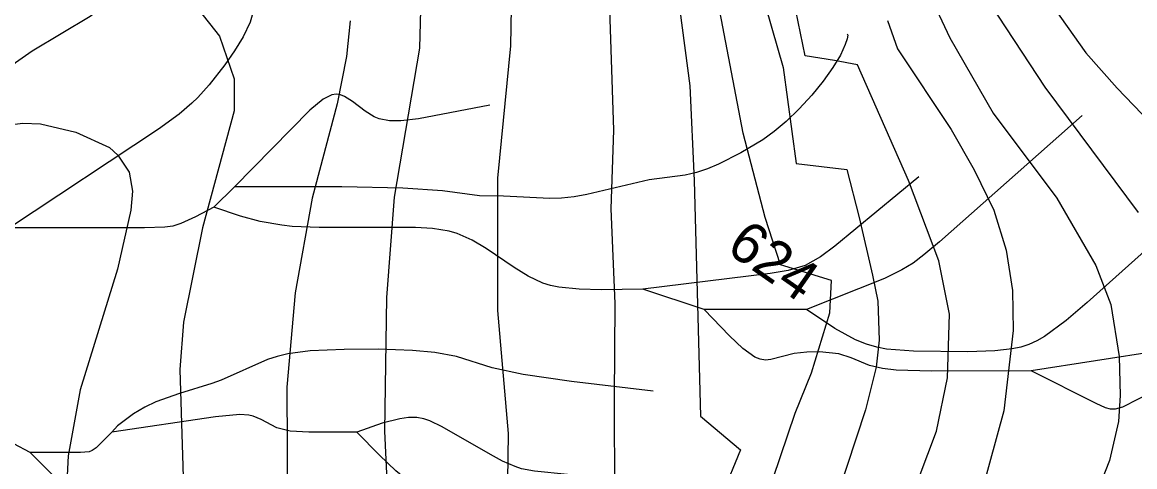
# Model space of a CAD drawing. Extents: x -709584 to -702006, y -1161789 to -1157496.
# Drawn here: x -707673.9 to -707401.6, y -1161265.5 to -1161156.7 of the extents above; entities that cross this region are included whole.
import ezdxf

# ---------------------------------------------------------------- set-up
doc = ezdxf.new("R2010")
doc.units = 0
for name, color, linetype in [('120_vrstevnice hlavní', 7, 'Continuous'), ('121_vrstevnice hlavní_popis', 7, 'Continuous'), ('122_vrstevnice základní', 7, 'Continuous'), ('411_akumulovaný odtok', 7, 'Continuous')]:
    doc.layers.add(name, color=color, linetype=linetype)

msp = doc.modelspace()

# ---------------------------------------------------------------- linework, layer by layer
at = {"layer": '120_vrstevnice hlavní'}
for points in [[(-707595.55, -1161031.98), (-707575.3, -1161055.13), (-707565.31, -1161068), (-707561.41, -1161075.96), (-707557.07, -1161087.24), (-707540.15, -1161115.88), (-707538.41, -1161119.64), (-707533.49, -1161134.68), (-707530.17, -1161153.48), (-707529.2, -1161183.13), (-707529.88, -1161202.37), (-707528.86, -1161225.52), (-707529.01, -1161248.66), (-707528.99, -1161272.92), (-707530.12, -1161282.34), (-707527.85, -1161284.68), (-707520.7, -1161289.88), (-707524.46, -1161298.17), (-707529.63, -1161309.29), (-707534.15, -1161320.98), (-707537.75, -1161331.12), (-707545.29, -1161343.18), (-707552.99, -1161352.64), (-707566.55, -1161362.44)], [(-707462.13, -1161156.29), (-707459.66, -1161163.19), (-707446.56, -1161182.99), (-707440.92, -1161192.83), (-707436.15, -1161202.66), (-707433.11, -1161212.5), (-707431.52, -1161222.33), (-707431.37, -1161232.17), (-707433.69, -1161251.84), (-707439.04, -1161271.51)], [(-707691.16, -1161183.57), (-707673.8, -1161181.4), (-707669.46, -1161181.54), (-707660.78, -1161183.57), (-707652.54, -1161187.33), (-707650.51, -1161189.21), (-707647.76, -1161193.41), (-707646.89, -1161198.03), (-707647.33, -1161202.66), (-707650.59, -1161217.15), (-707659.77, -1161246.64), (-707662.66, -1161262.84), (-707663.09, -1161270.94), (-707661.5, -1161292.34), (-707662.08, -1161305.36), (-707664.25, -1161318.38), (-707666.57, -1161327.06), (-707672.64, -1161340.08), (-707681.46, -1161353.24)]]:
    msp.add_lwpolyline(points, dxfattribs=at)
at = {"layer": '122_vrstevnice základní'}
for points in [[(-707482.27, -1161164.89), (-707493.14, -1161112.12)], [(-707497.72, -1161132.85), (-707487.65, -1161167.77)], [(-707454.77, -1161143.59), (-707446.85, -1161160.55), (-707436.29, -1161178.94), (-707420.67, -1161199.77), (-707411.12, -1161216.26), (-707407.51, -1161225.81), (-707405.48, -1161238.53), (-707405.19, -1161248.08), (-707405.63, -1161254.45), (-707407.8, -1161263.99), (-707411.56, -1161273.54), (-707424.43, -1161301.6), (-707430.51, -1161321.85), (-707438.75, -1161359.46), (-707443.09, -1161376.81), (-707446.27, -1161385.49), (-707449.89, -1161391.28), (-707459.72, -1161400.83), (-707475.35, -1161410.08), (-707494.15, -1161418.47), (-707528.87, -1161431.2), (-707554.9, -1161444.65), (-707571.1, -1161457.09), (-707587.4, -1161472.28)], [(-707488.36, -1161216.11), (-707492.07, -1161204.47), (-707497.48, -1161183.86), (-707505.29, -1161142.78)], [(-707660.66, -1161419.36), (-707668.58, -1161408.8), (-707654.42, -1161394.03), (-707622.59, -1161363.22), (-707612.32, -1161351.36), (-707601.48, -1161336.03), (-707594.39, -1161321.85), (-707591.5, -1161313.61), (-707585.13, -1161286.56), (-707584.41, -1161272.38), (-707585.13, -1161256.76), (-707584.7, -1161224.07), (-707582.82, -1161199.48), (-707576.6, -1161163.03), (-707576.16, -1161147.41)], [(-707400.71, -1161203.24), (-707423.56, -1161172.58), (-707438.75, -1161149.43)], [(-707630.84, -1161153.48), (-707625.63, -1161160.14), (-707622.02, -1161170.55), (-707622.02, -1161178.36), (-707629.83, -1161207), (-707634.46, -1161230.15), (-707635.32, -1161241.72), (-707634.31, -1161275.85), (-707634.6, -1161283.95), (-707636.33, -1161295.53), (-707639.08, -1161307.1), (-707643.42, -1161320.11), (-707646.75, -1161327.93), (-707653.55, -1161340.94), (-707664.97, -1161359.17), (-707678.28, -1161375.66), (-707706.34, -1161405.17), (-707719.94, -1161421.08), (-707728.1, -1161434.06), (-707740.16, -1161454.79), (-707746.94, -1161467.23), (-707740.16, -1161476.28)], [(-707596.69, -1161372.62), (-707603.85, -1161362.44), (-707594.81, -1161350.38), (-707589.91, -1161343.6), (-707579.74, -1161330.78), (-707568.64, -1161316.06), (-707564.3, -1161307.1), (-707558.32, -1161292.38), (-707556.78, -1161285.11), (-707555.05, -1161268.91), (-707554.9, -1161257.34), (-707557.5, -1161227.25), (-707557.5, -1161194.85), (-707554.32, -1161162.45), (-707554.18, -1161153.2)], [(-707422.7, -1161151.17), (-707413.58, -1161164.19), (-707405.92, -1161172.87), (-707365.27, -1161215.1)], [(-707512.95, -1161153.77), (-707510.49, -1161172.29), (-707509.48, -1161195.43), (-707507.89, -1161253.09), (-707498.09, -1161261.38), (-707502.61, -1161272.31), (-707512.41, -1161296.44), (-707517.87, -1161313.75), (-707523.66, -1161329.37), (-707528.14, -1161337.18), (-707534.9, -1161348.12), (-707543.57, -1161357.92), (-707550.73, -1161363.95), (-707560.15, -1161370.36), (-707573.71, -1161378.27)], [(-707593.67, -1161156.38), (-707594.53, -1161165.06), (-707596.85, -1161176.63), (-707602.92, -1161199.77), (-707607.12, -1161222.91), (-707609.14, -1161246.06), (-707609, -1161275.56), (-707610.16, -1161286.27), (-707612.04, -1161294.08), (-707616.52, -1161307.1), (-707621.44, -1161317.51), (-707631.42, -1161335.74), (-707637.93, -1161346.15)], [(-707456.98, -1161195.43), (-707469.46, -1161167.15), (-707475.11, -1161166.02), (-707482.27, -1161164.89)], [(-707487.65, -1161167.77), (-707484.53, -1161191.28), (-707472.1, -1161192.78), (-707469.08, -1161204.47), (-707465.8, -1161218.57), (-707464.5, -1161224.94), (-707464.21, -1161234.49), (-707464.93, -1161241.14), (-707467.54, -1161251.55), (-707478.96, -1161286.27)], [(-707622.16, -1161470.26), (-707615.07, -1161460.85), (-707605.09, -1161450.58), (-707591.35, -1161438.29), (-707579.49, -1161428.89), (-707566.47, -1161419.78), (-707545.79, -1161409.79), (-707530.6, -1161404.01), (-707503.12, -1161391.42), (-707497.62, -1161387.95), (-707489.52, -1161381.44), (-707481.85, -1161372.48), (-707478.67, -1161366.69), (-707476.5, -1161360.9), (-707474.62, -1161352.66), (-707473.32, -1161345.28), (-707473.18, -1161340.08), (-707470.14, -1161316.64), (-707462.91, -1161290.61), (-707450.18, -1161256.76), (-707447.43, -1161243.74), (-707447, -1161228.12), (-707449.6, -1161215.1), (-707456.98, -1161195.43)], [(-707674.23, -1161496.63), (-707670.46, -1161486.83), (-707661.42, -1161468.36), (-707653.65, -1161456.95), (-707635.86, -1161435.98), (-707626.76, -1161428.41), (-707610.93, -1161415.59), (-707591.72, -1161403.15), (-707559.24, -1161384.48), (-707548.25, -1161377.83), (-707535.08, -1161368.57), (-707527.42, -1161362.35), (-707515.99, -1161350.63), (-707511.51, -1161343.84), (-707506.16, -1161332.27), (-707502.39, -1161320.69), (-707501.09, -1161314.91), (-707498.06, -1161293.21), (-707490.12, -1161268.28), (-707484.77, -1161252.37), (-707480.76, -1161242.54), (-707476.24, -1161227.84), (-707475.86, -1161219.92), (-707488.36, -1161216.11)]]:
    msp.add_lwpolyline(points, dxfattribs=at)
at = {"layer": '411_akumulovaný odtok'}
for p, q in [((-707621.99, -1161197), (-707626.99, -1161202)), ((-707506.99, -1161227), (-707521.99, -1161222)), ((-707481.99, -1161227), (-707506.99, -1161227)), ((-707394.49, -1161237), (-707426.99, -1161242))]:
    msp.add_line(p, q, dxfattribs=at)
for points in [[(-707661.99, -1161137), (-707663.17, -1161138.18), (-707664.12, -1161139.85), (-707664.33, -1161140.81), (-707664.21, -1161141.89), (-707663.75, -1161142.94), (-707663.02, -1161143.93), (-707662.11, -1161144.82), (-707657.05, -1161148.45), (-707655.34, -1161149.87), (-707654.26, -1161151.27), (-707654.12, -1161151.96), (-707654.33, -1161152.63), (-707655.49, -1161153.95), (-707657.25, -1161155.26), (-707671.46, -1161163.74), (-707675.57, -1161166.65), (-707676.56, -1161167.67), (-707678.42, -1161170.19), (-707680.01, -1161172.94), (-707681.99, -1161177)], [(-707606.99, -1161137), (-707608.16, -1161137.48), (-707610.58, -1161139.1), (-707611.94, -1161140.32), (-707613.24, -1161141.81), (-707614.35, -1161143.56), (-707615.26, -1161145.5), (-707615.97, -1161147.53), (-707617.62, -1161154.95), (-707618.14, -1161156.65), (-707619.82, -1161160.27), (-707621.96, -1161163.73), (-707624.33, -1161167.1), (-707628.16, -1161172), (-707630.9, -1161175.09), (-707632.36, -1161176.54), (-707635.51, -1161179.2), (-707640.54, -1161182.85), (-707676.99, -1161207)], [(-707471.99, -1161159.5), (-707471.87, -1161159.87), (-707472.02, -1161160.79), (-707472.46, -1161162.18), (-707473.67, -1161164.72), (-707475.5, -1161167.75), (-707477.88, -1161171.08), (-707480.66, -1161174.51), (-707483.72, -1161177.87), (-707486.93, -1161180.96), (-707489.87, -1161183.43), (-707492.66, -1161185.44), (-707498.03, -1161188.68), (-707503.47, -1161191.45), (-707506.2, -1161192.59), (-707508.92, -1161193.51), (-707511.63, -1161194.14), (-707520.48, -1161195.27), (-707535.72, -1161198.89), (-707538.82, -1161199.45), (-707541.91, -1161199.79), (-707544.82, -1161199.85), (-707556.1, -1161199.24), (-707562.02, -1161199.17), (-707571.05, -1161197.96), (-707580.78, -1161197.3), (-707595.72, -1161197.01), (-707621.99, -1161197)], [(-707559.49, -1161177), (-707576.96, -1161180.33), (-707581.24, -1161180.83), (-707583.99, -1161180.85), (-707586.59, -1161180.35), (-707587.75, -1161179.85), (-707589.94, -1161178.48), (-707593.04, -1161176.13), (-707595.05, -1161174.85), (-707596.05, -1161174.44), (-707597.05, -1161174.28), (-707598.13, -1161174.43), (-707600.29, -1161175.52), (-707603.54, -1161178.21), (-707621.99, -1161197)], [(-707414.49, -1161179.5), (-707449.45, -1161210.45), (-707453.26, -1161213.65), (-707455.89, -1161215.64), (-707458.61, -1161217.34), (-707462.84, -1161219.41), (-707481.99, -1161227)], [(-707454.49, -1161194.5), (-707475.05, -1161211.52), (-707478.57, -1161214.14), (-707482.3, -1161216.27), (-707486.45, -1161217.5), (-707490.82, -1161218.24), (-707521.99, -1161222)], [(-707384.49, -1161199.5), (-707413.28, -1161225.3), (-707418.41, -1161229.72), (-707423.74, -1161233.64), (-707425.6, -1161234.72), (-707427.54, -1161235.59), (-707429.53, -1161236.21), (-707431.59, -1161236.65), (-707435.86, -1161237.13), (-707442.46, -1161237.36), (-707455.81, -1161237.21), (-707462.38, -1161236.73), (-707464.75, -1161236.27), (-707467.3, -1161235.5), (-707469.95, -1161234.41), (-707475.03, -1161231.68), (-707481.99, -1161227)], [(-707626.99, -1161202), (-707631.53, -1161204.36), (-707635.09, -1161205.97), (-707637.09, -1161206.58), (-707639.02, -1161206.87), (-707643.98, -1161207.05), (-707676.99, -1161207)], [(-707521.99, -1161222), (-707532.17, -1161222.18), (-707537.64, -1161222.05), (-707542.6, -1161221.57), (-707544.62, -1161221.15), (-707546.51, -1161220.57), (-707550.1, -1161218.85), (-707553.55, -1161216.7), (-707560.34, -1161212.08), (-707563.82, -1161210), (-707567.44, -1161208.38), (-707569.41, -1161207.84), (-707573.48, -1161207.2), (-707577.67, -1161206.93), (-707601.24, -1161206.91), (-707607.81, -1161206.68), (-707610.39, -1161206.4), (-707615.66, -1161205.43), (-707620.48, -1161204.15), (-707626.99, -1161202)], [(-707426.99, -1161242), (-707451.39, -1161242.1), (-707460, -1161241.84), (-707463.33, -1161241.46), (-707466.51, -1161240.72), (-707471.05, -1161238.85), (-707474.08, -1161237.9), (-707478.76, -1161237.37), (-707481.92, -1161237.42), (-707484.99, -1161237.77), (-707490.7, -1161239.29), (-707492.02, -1161239.4), (-707493.31, -1161239.18), (-707494.59, -1161238.65), (-707497.56, -1161236.52), (-707500.84, -1161233.48), (-707506.99, -1161227)], [(-707519.49, -1161247), (-707539.48, -1161244.66), (-707551.27, -1161242.95), (-707558.88, -1161241.31), (-707567.65, -1161238.52), (-707572.91, -1161237.52), (-707578.36, -1161237.03), (-707586.71, -1161236.76), (-707595.11, -1161236.77), (-707603.45, -1161237.16), (-707608.87, -1161237.87), (-707611.51, -1161238.48), (-707613.86, -1161239.25), (-707625.22, -1161244.28), (-707627.53, -1161245.16), (-707635.43, -1161247.55), (-707641.24, -1161249.64), (-707643.94, -1161250.92), (-707646.64, -1161252.52), (-707650.58, -1161255.52), (-707651.99, -1161257)], [(-707396.99, -1161247), (-707404.63, -1161250.9), (-707406.4, -1161251.41), (-707407.57, -1161251.39), (-707408.75, -1161251.07), (-707411.1, -1161250.03), (-707426.99, -1161242)], [(-707591.99, -1161257), (-707603.75, -1161257.07), (-707608.37, -1161256.76), (-707611.58, -1161255.99), (-707615.41, -1161253.95), (-707617.36, -1161253.11), (-707618.43, -1161252.87), (-707620.69, -1161252.73), (-707626.61, -1161253.27), (-707651.99, -1161257)], [(-707511.99, -1161272), (-707512.87, -1161272.93), (-707513.93, -1161273.56), (-707515.32, -1161274.07), (-707516.94, -1161274.32), (-707518.75, -1161274.29), (-707520.67, -1161274.02), (-707524.47, -1161272.95), (-707532.4, -1161269.51), (-707537.2, -1161267.95), (-707540.42, -1161267.42), (-707548.55, -1161266.62), (-707551.71, -1161265.98), (-707553.29, -1161265.47), (-707556.35, -1161264.13), (-707559.34, -1161262.54), (-707571.14, -1161255.7), (-707574.12, -1161254.3), (-707575.63, -1161253.78), (-707577.35, -1161253.48), (-707579.35, -1161253.49), (-707581.49, -1161253.77), (-707585.8, -1161254.83), (-707591.99, -1161257)], [(-707651.99, -1161257), (-707655.8, -1161260.86), (-707656.76, -1161261.55), (-707657.5, -1161261.84), (-707659.62, -1161262.04), (-707671.99, -1161262)], [(-707504.49, -1161302), (-707505.97, -1161302.06), (-707509.62, -1161301.74), (-707514.3, -1161300.73), (-707518.79, -1161298.91), (-707525.52, -1161295.37), (-707526.95, -1161294.92), (-707531.93, -1161294.31), (-707533.42, -1161293.73), (-707536.42, -1161291.81), (-707545.79, -1161284.17), (-707549.3, -1161282.01), (-707555, -1161279.48), (-707570.85, -1161273.81), (-707574.65, -1161272.14), (-707576.46, -1161271.16), (-707578.37, -1161269.88), (-707582.49, -1161266.47), (-707586.48, -1161262.67), (-707591.99, -1161257)], [(-707671.99, -1161262), (-707675.98, -1161259.93), (-707678.89, -1161258.71), (-707681.87, -1161257.87), (-707683.27, -1161257.72), (-707685.76, -1161257.85), (-707689.5, -1161258.42), (-707703.22, -1161261.27), (-707706.83, -1161262.39), (-707711.34, -1161264.58), (-707731.99, -1161277)], [(-707651.99, -1161272), (-707659.63, -1161272.06), (-707661.85, -1161271.68), (-707662.97, -1161270.98), (-707664.01, -1161270.05), (-707671.99, -1161262)]]:
    msp.add_lwpolyline(points, dxfattribs=at)

# ---------------------------------------------------------------- texts
at = {"layer": '121_vrstevnice hlavní_popis'}
msp.add_text('624', height=10, rotation=325.0011, dxfattribs=at).set_placement((-707501.96, -1161212.7))

doc.saveas('drawing.dxf')
